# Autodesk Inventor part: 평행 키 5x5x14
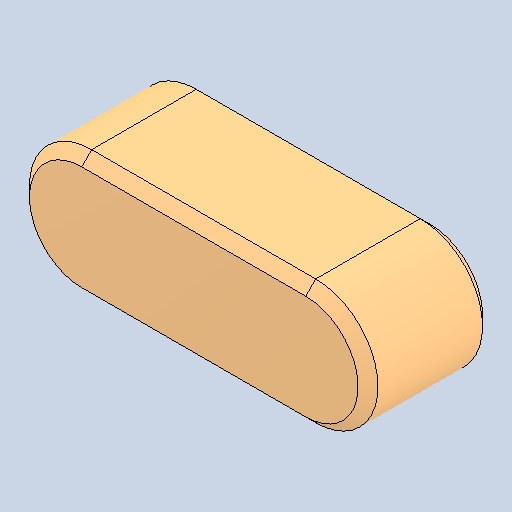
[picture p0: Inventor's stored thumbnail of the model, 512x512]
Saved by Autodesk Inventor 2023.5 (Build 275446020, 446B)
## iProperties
Created: 2026-07
Part Number: 평행 키 5x5x14
Material: 강철, 연강
Document SubType Name: Modeling
Designer: mirae
Density: 7.86 g/cm^3
Appearance: 기본값
Author: jhkim
Revision Number: 1
Sending System: Autodesk Inventor 2027
Preprocessor: ST-DEVELOPER v20.1
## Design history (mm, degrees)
node "평행 키 5x5x141"
node "솔리드2"
node "솔리드1"
